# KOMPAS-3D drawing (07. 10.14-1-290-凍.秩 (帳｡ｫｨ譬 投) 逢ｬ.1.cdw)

Views: Вид 1
Referenced files: Таблица УК.cdw
Referenced files in X:\Проекты\ПС 110 кВ Северные ЭС\5. ПС Опорная\2. Проект\04-РЗА\Рабочая документация\290-УА\: 07. 10.14-1-290-УА.ТБ (Таблица УК).cdw
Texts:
  Текст на чертеже
  Размерные надписи
  Шероховатость
  Линия-выноска #1
  Линия-выноска #2
  Линия-выноска #3
  Отклонения формы и база
  Заголовок таблицы
  Ячейка таблицы
  Стрелка вида
  Обозначение изменения
  Фигурная скобка
  Номер узла
  Марка координационной оси
  VRCB
  Выносная надпись
  Обозначение узла
  Марка/позиционное обозначение с линией-выноской
  Марка/позиционное обозначение на линии
  Марка/позиционное обозначение без линии-выноски
  Состав чартежа
  ячейка табл.
  маркировка
  Маркировка
  Аппараты
  Подпись в квадратике
  ссылки
  цепи
  Без имени
  rustxt
  russ
  Normal
  Лит-Масса-Масштаб
  Материал-Предприятие
  Title Specification
  Body Specification ( left align )
  Body Specificaton ( centered )
  табл
  Additional DXF text style 0
  Обычный
  Термин
  Список определений
  Адрес
  Цитаты
  Форматированный
  Courier New
  Z-конец формы
  Z-начало формы
  Body Text
  ЗОНА_привяз
  txt
  Simplex
  Txt
  heading 1
  Знак Знак Знак Знак Знак Знак
  Verdana
  heading 2
  AGOpus
  footer
  MS Sans Serif
  ТекстШаг1
  Тексты. 3,2
  Body Text 3
  Title
  heading 8
  heading 3
  heading 6
  heading 7
  ООббыыччнныыйй
  ТТееррммиинн
  ССппииссоокк ооппррееддееллеенниийй
  ААддрреесс
  ЦЦииттааттыы
  ФФооррммааттиирроовваанннныыйй
  Z-ккооннеецц ффооррммыы
  Z-ннааччааллоо ффооррммыы
  Абзац Знак
  heading 4
  heading 5
  heading 9
  текст переноса
  клеммы, контакты
  тексты табл
  Table Contents
  Table Heading
  Tahoma
  Денис
  подписи
  Ссылки
  Пояснения
  Definition Term
  Definition List
  Address
  Blockquote
  Preformatted
  z-Bottom of Form
  z-Top of Form
  header
  Текст 3,5
  ГОСТ_МНЕ
  ESK - Обозначение
  Клеммник текст
  Body Text Indent 3
  Основной текст с отступом 3
  TXT
  GOST 2.304 type A
  ISOCP
  style2
  Шрифт 2.5
  Заголовки
  HeliosLight
  Pa3
  Pa1
  RUSTXT
  romanc
  CM12
  romans
  NormalParagraphStyle
  FR5
  Subtitle
  Три с половиной
  eskd1
  Pa15
  Pa18
  терминал
  CNBNDG+TimesNewRoman
  gif
  Пояснения 2
  текст табл
  ISOCPEUR
  CC С?т?и?л?ь? П?о? ц?е?н?т?р?у?
  Adobe Gothic Std B
  Новое оборудование
  .07 RGB_0_0_0 i0b0u0
  Позиционное
  обозначение и номер
  монтажной единицы
  Кол-
  Шкаф 5Р. Шкаф ТН 110 кВ, ТН 6 кВ и элегаз
  Выключатель нагрузки ABB OT40F4, Iн=40А
  Светильник IP 44-3 60 Вт/Е27
  Выключатель Rittal PS 4127.000
  Выключатель автоматический
  Амперметр
  ЩП120П-100мА-220ВУ-1RS-x-3-0,5
  Вольтметр
  ЩП120П-110кВ/100В-220ВУ-1RS-x-3-0,5
  Резистор С5-35В-15-150 Ом 5%
  Кнопка
  LOVATO 8LM2T AU120+8LM2T B102+8LM2T C10
  Переключатель APATOR 4G10-66-U-R014
  ЩП120П-6кВ/100В-220ВУ-1RS-x-3-0,5
  Лампа светодиодная индикаторная
  СКЛ 11Б-Ж-2-220
  СКЛ 11Б-К-2-220
  Реле двухпозиционное РЭП-38Д-1,
  постоянного тока, 220 В
  Диод 1N4007
  Выключатель автоматический АВВ
  S282 UC-Z3, 220В, 3А
  Вспомогательный/сигнальный контакт
  АВВ S2-S/H, 250 В, 0,5 А
  S282 UC-Z6, 220В, 6А
  Дистанционный расцепитель
  Рамка для надписи малая
  Монтажная рейка TS 35X7.5/LL 2M/ST/ZN
  Желтая
  Красная
  для SF4,SF5,
  SF14,SF15
  Копировал                          Формат    А4
  Крепежный винт KISK M3x20 SAC10 CU5
  Винтовой соединительный мостик QL 4 SAC6N
  Групповой держатель шильдиков SchT 5
  Маркировочный шильдик DEK 8
  Перемычки:
  Винтовой соединительный мостик QL 2 SAC6N
  Концевая пластина WAP WTL6/1
  Концевой стопор WEW 35/2
  Гнездо STB 14
  Клемма проходная WTD 6/1
  Клемма измерительная WTL 6/1/STB
  Винтовой соединительный мостик QL 6 SAC6N
  Соединительная муфта VH 12/4.9/3.3 SAC6N
  Клеммный ряд в составе:
  для
  WTD 6/1
  Шкаф сигнализации РЗТ
  Реле РУ 21/0,5, постоянного тока,
  утопленного монтажа
  Клеммный блок Weidmuller KIT KLTR 4TR POCON8
  Рабочая крышка Weidmuller SD ST 4TR POCON8
  Кодирующий элемент Weidmuller KOEL POCON
  Монтажная рейка TS 35X7.5/LL 1M/ST/ZN
  Концевая пластина WAP WTL 6/1
  Таблицы
  Таблица УК и технических
  данных аппаратуры по заказу
  Борисов
  Разраб.
  Алдошина
  Н.контр.
  Зам.
Dimensions and other numbers on the sheet: 10/14-1-290-УА.ТБ; 7; 3,2 (надписи); 2,5 (контакты, клеммы); 3,2_; 2,5; 5_заголовок; 3,2; 3,5_01; 2,5_01; 3,5_tabl; 2,3_; 2,5_3; 3,2_зона не привяз; 3.2 фиол; 2,5 грязносинь; 3.5; 2.5; 1,8; 2.5 курсив; 3,5; 5; 3,2 элементы; 3,2 линия; 3,2 таблица; 3.2 маркировка; 2.5_Э5_надписи; 2.5_Э5_ссылки; 2.5_кабель; 3.2; 2.5 надписи; 3,2 (Зоны); 3.2 (текст); 5,0_белый_подчёркнутый; 5 ШРИФТ; 3 и 5; 0 i0b0u0; 04-S1...04-S3; 00-EL1; 00-SB1; 00-SF1; 01-PA1; 01-PV1; 01-R1; 01-SB1; 01-SN1; 02-PV1, 02-PV2; 02-SN1, 02-SN2; 03-HL1, 03-HL3,; 03-HL5; 03-HL2, 03-HL4,; 03-HL6; 03-KL1...03-KL6; 03-SB1, 03-SB2; 03-VD1...03-VD6; 04-SF1...04-SF3,; 04-SF5...04-SF13,; 04-SF15...04-SF20; 04-SF4, 04-SF14; 3; 1; 2; 6; 18; 20; 4; 36; 114; 21; 255; 63; 192; 01-КН1, 01-КН2,; 02-КН1, 02-КН2; 01-SG1, 02-SG1; 28; 32; 60; 11.09/125.003-290-ЭП.ТБ-; 11.12; 08.13; 678-13; 10/14-1-290-УА.ТБ-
